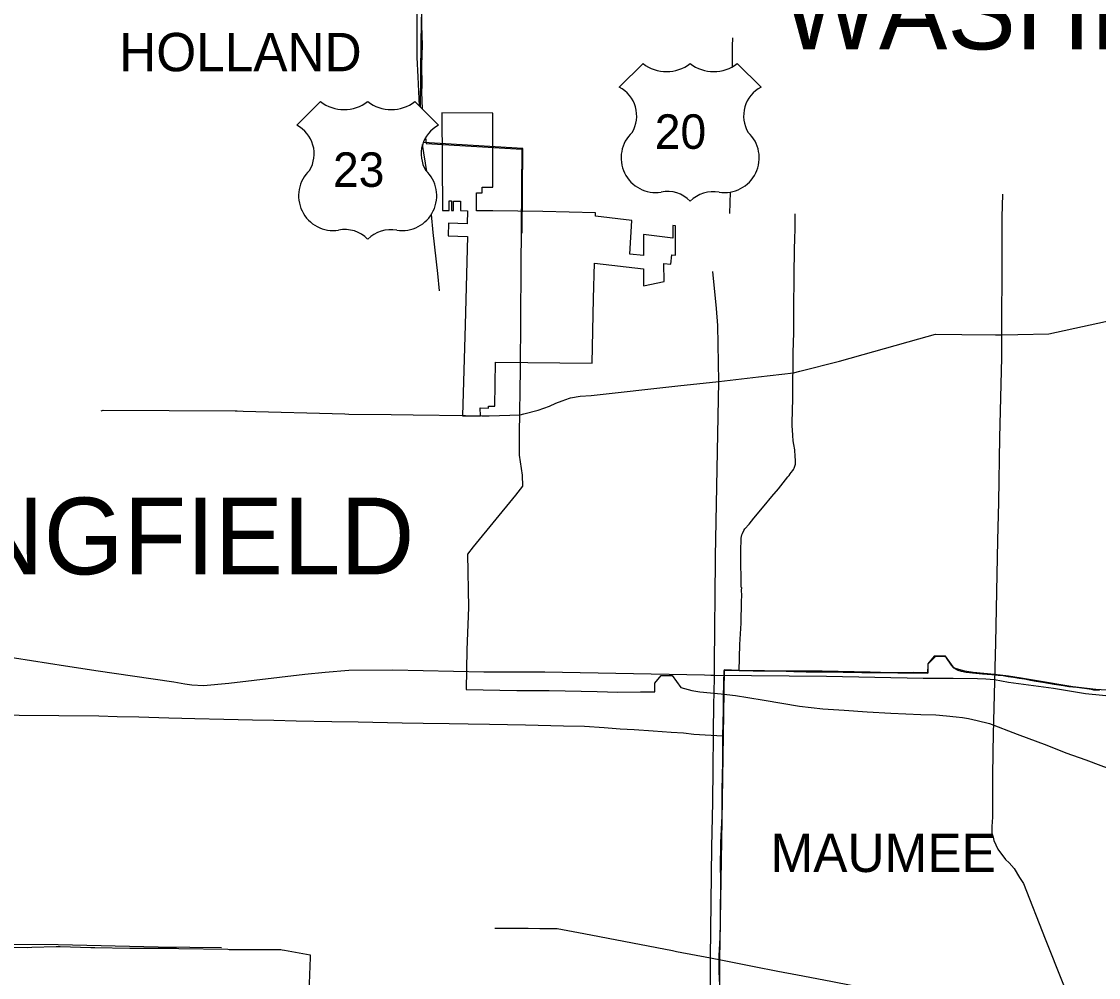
# Model space of a CAD drawing. Extents: x -232 to 448, y 619 to 1059.
# Drawn here: x 113.08 to 141.87, y 900.18 to 925.75 of the extents above; entities that cross this region are included whole.
import ezdxf

# ---------------------------------------------------------------- set-up
doc = ezdxf.new("R2010")
doc.units = 0
doc.layers.add('Default', color=7, linetype='Continuous')

msp = doc.modelspace()

# ---------------------------------------------------------------- linework, layer by layer
at = {"layer": 'Default'}
for p, q in [((129.69, 924.629), (129.056, 923.995)), ((129.69, 924.629), (129.056, 923.995)), ((132.845, 923.995), (132.211, 924.629)), ((132.845, 923.995), (132.211, 924.629)), ((121.069, 923.613), (120.435, 922.979)), ((121.069, 923.613), (120.435, 922.979)), ((124.224, 922.979), (123.59, 923.613)), ((124.224, 922.979), (123.59, 923.613)), ((124.312, 923.312), (124.329, 920.698)), ((125.678, 923.298), (124.312, 923.312)), ((125.391, 921.173), (125.392, 921.321)), ((125.392, 921.321), (125.675, 921.32)), ((125.242, 920.688), (125.242, 921.173)), ((125.242, 921.173), (125.391, 921.173)), ((124.329, 920.698), (124.508, 920.696)), ((124.508, 920.696), (124.51, 920.952)), ((124.51, 920.952), (124.574, 920.952)), ((124.574, 920.952), (124.571, 920.695)), ((124.571, 920.695), (124.622, 920.695)), ((124.622, 920.695), (124.625, 920.951)), ((124.625, 920.951), (124.815, 920.949)), ((124.815, 920.949), (124.812, 920.693)), ((124.49, 920.359), (124.479, 920.017)), ((124.99, 920.344), (124.49, 920.359)), ((130.489, 920.293), (130.489, 919.954)), ((130.558, 919.503), (130.557, 920.285)), ((124.479, 920.017), (124.997, 920.001)), ((129.703, 920.059), (129.702, 919.494)), ((130.489, 919.954), (129.703, 920.059)), ((129.702, 919.494), (129.342, 919.53)), ((128.391, 919.292), (129.701, 919.138)), ((130.253, 918.8), (130.246, 919.278)), ((130.246, 919.278), (130.435, 919.258)), ((130.435, 919.258), (130.461, 919.513)), ((130.461, 919.513), (130.558, 919.503)), ((129.701, 919.138), (129.7, 918.678)), ((129.7, 918.678), (130.253, 918.8)), ((125.731, 915.467), (125.745, 916.637)), ((125.561, 915.467), (125.731, 915.467))]:
    msp.add_line(p, q, dxfattribs=at)
for points in [[(123.714, 923.489), (123.675, 924.275), (123.65, 924.788), (123.649, 925.61), (123.641, 927.333), (123.627, 928.289), (123.622, 929.819), (123.618, 930.906), (123.63, 931.3), (123.629, 931.909), (123.655, 932.491), (123.72, 933.201), (123.778, 933.589), (123.941, 934.95), (124.022, 935.605), (124.069, 936.394), (124.077, 937.169), (124.04, 938.101), (124.013, 938.481)], [(123.745, 923.459), (123.764, 925.219), (123.875, 930.909), (124.356, 930.897), (124.373, 933.632)], [(123.806, 928.062), (123.767, 925.651), (123.782, 925.123), (123.772, 924.588), (123.778, 924.041), (123.766, 923.865)], [(132.078, 925.315), (132.074, 925.089), (132.07, 924.536)], [(123.766, 923.865), (123.79, 923.416)], [(125.675, 921.32), (125.678, 923.298)], [(123.913, 921.739), (123.795, 922.46)], [(126.457, 920.09), (126.481, 922.358), (123.82, 922.518)], [(123.876, 922.648), (123.896, 922.491)], [(123.896, 922.491), (126.452, 922.34)], [(126.452, 922.34), (126.428, 919.164), (126.409, 916.455)], [(132.02, 921.189), (132.002, 920.619)], [(139.303, 921.136), (139.284, 920.523), (139.286, 919.899)], [(124.812, 920.693), (125.001, 920.691)], [(125.001, 920.691), (124.99, 920.344)], [(125.672, 920.684), (125.242, 920.688)], [(128.42, 920.639), (127.016, 920.67), (125.672, 920.684)], [(124.253, 918.546), (124.205, 919.013), (124.083, 920.113), (124.033, 920.593)], [(128.42, 920.545), (128.42, 920.639)], [(129.388, 920.427), (128.42, 920.545)], [(129.342, 919.53), (129.388, 920.427)], [(132.263, 908.385), (132.282, 909.092), (132.31, 909.661), (132.325, 910.236), (132.332, 910.395), (132.326, 910.543), (132.333, 910.6), (132.313, 910.625), (132.313, 910.868), (132.309, 911.248), (132.306, 911.67), (132.31, 911.832), (132.314, 911.933), (132.321, 911.98), (132.33, 912.021), (132.349, 912.061), (132.387, 912.141), (132.416, 912.18), (132.529, 912.309), (132.65, 912.47), (132.925, 912.798), (133.13, 913.044), (133.309, 913.251), (133.436, 913.413), (133.565, 913.569), (133.597, 913.612), (133.628, 913.655), (133.653, 913.689), (133.691, 913.744), (133.716, 913.772), (133.735, 913.805), (133.752, 913.86), (133.763, 913.916), (133.768, 913.965), (133.767, 914.018), (133.754, 914.119), (133.745, 914.296), (133.723, 914.436), (133.706, 914.539), (133.696, 914.683), (133.682, 914.828), (133.675, 914.924), (133.678, 915.07), (133.687, 915.296), (133.694, 915.711), (133.696, 916.104), (133.701, 916.521), (133.707, 916.903), (133.718, 917.427), (133.721, 917.867), (133.721, 918.122), (133.725, 918.379), (133.735, 918.63), (133.732, 918.922), (133.734, 919.195), (133.74, 919.421), (133.742, 919.713), (133.749, 919.883), (133.759, 920.259), (133.759, 920.607)], [(130.557, 920.285), (130.489, 920.293)], [(124.997, 920.001), (124.939, 917.64)], [(139.286, 919.899), (139.286, 919.443), (139.275, 917.373)], [(139.707, 917.382), (140.54, 917.4), (142.541, 917.833), (146.021, 918.829), (149.248, 919.837)], [(128.369, 918.347), (128.391, 919.292)], [(131.717, 916.125), (131.694, 917.618), (131.657, 918.076), (131.555, 919.063)], [(128.329, 916.614), (128.369, 918.347)], [(124.939, 917.64), (124.863, 915.202)], [(133.88, 916.4), (134.947, 916.67), (137.061, 917.265)], [(137.061, 917.265), (137.511, 917.392), (138.212, 917.384)], [(138.212, 917.384), (139.116, 917.374)], [(139.116, 917.374), (139.275, 917.373)], [(139.275, 917.373), (139.269, 916.758), (139.224, 914.628), (139.189, 912.895)], [(139.275, 917.373), (139.707, 917.382)], [(126.409, 916.455), (126.376, 914.719), (126.381, 914.149), (126.463, 913.62), (126.468, 913.322), (126.284, 913.084), (125.153, 911.7), (124.995, 911.509)], [(125.745, 916.637), (128.329, 916.614)], [(132.774, 916.248), (133.715, 916.358), (133.88, 916.4)], [(130.619, 916.003), (131.717, 916.125)], [(131.625, 911.332), (131.626, 911.44), (131.717, 916.125)], [(131.717, 916.125), (132.774, 916.248)], [(127.721, 915.675), (127.751, 915.685), (128.008, 915.731), (128.308, 915.748), (130.619, 916.003)], [(126.502, 915.257), (126.889, 915.354), (127.19, 915.461), (127.36, 915.548), (127.526, 915.608), (127.721, 915.675)], [(115.201, 915.341), (115.258, 915.36), (118.784, 915.336), (118.838, 915.335)], [(118.838, 915.335), (119.001, 915.33)], [(119.001, 915.33), (121.716, 915.256)], [(121.716, 915.256), (121.825, 915.253), (122.956, 915.239)], [(122.956, 915.239), (123.548, 915.232)], [(123.548, 915.232), (124.948, 915.215)], [(124.863, 915.202), (125.342, 915.201), (125.341, 915.42), (125.561, 915.414)], [(124.948, 915.215), (125.379, 915.209)], [(125.379, 915.209), (125.578, 915.207), (126.408, 915.233), (126.502, 915.257)], [(125.561, 915.414), (125.561, 915.467)], [(115.144, 907.168), (111.936, 907.2), (111.904, 905.094), (110.356, 905.131), (104.888, 905.043), (104.921, 907.765), (104.984, 912.994), (105.011, 913.263)], [(139.189, 912.895), (139.169, 911.87), (139.11, 909.135), (139.094, 908.473)], [(124.995, 911.509), (125.024, 910.074), (124.981, 908.945)], [(131.6, 908.588), (131.625, 911.332)], [(124.981, 908.945), (124.962, 907.881)], [(112.422, 908.8), (113.34, 908.658), (114.256, 908.517), (115.129, 908.386), (116.045, 908.246), (117.144, 908.086), (117.44, 908.04), (117.632, 908.011), (117.941, 907.996), (118.622, 908.052), (120.651, 908.297), (121.189, 908.349), (121.829, 908.398), (122.999, 908.413), (125.437, 908.359), (127.066, 908.361), (131.334, 908.274)], [(131.59, 907.727), (131.597, 908.297), (131.6, 908.588)], [(141.894, 907.857), (141.745, 907.87), (141.676, 907.886), (141.551, 907.9), (141.286, 907.935), (141.077, 907.957), (140.933, 907.98), (140.684, 908.021), (140.378, 908.071), (140.196, 908.102), (140.045, 908.127), (139.89, 908.159), (139.75, 908.182), (139.597, 908.207), (139.454, 908.227), (139.315, 908.248), (139.18, 908.261), (139.017, 908.273), (138.768, 908.298), (138.502, 908.323), (138.331, 908.338), (138.202, 908.369), (138.115, 908.395), (138.06, 908.42), (138.025, 908.443), (137.987, 908.471), (137.937, 908.533), (137.803, 908.735), (137.759, 908.77), (137.507, 908.768), (137.307, 908.558), (137.299, 908.311), (136.502, 908.322), (136.066, 908.327), (135.539, 908.335), (135.04, 908.339), (134.526, 908.347), (134.05, 908.347), (133.723, 908.358), (133.304, 908.371), (132.631, 908.371), (132.263, 908.385)], [(139.082, 908.285), (138.512, 908.338), (138.294, 908.374), (138.005, 908.454), (137.772, 908.779), (137.477, 908.777), (137.304, 908.575), (137.307, 908.334), (136.926, 908.338), (136.321, 908.334)], [(132.263, 908.397), (131.858, 908.408), (131.834, 906.654), (131.798, 904.383)], [(132.263, 908.385), (131.848, 908.392), (131.836, 907.685), (131.831, 907.33), (131.819, 906.639)], [(136.321, 908.334), (135.762, 908.35), (134.482, 908.378), (133.615, 908.378), (132.263, 908.397)], [(139.092, 908.365), (139.087, 908.15), (139.086, 908.096)], [(139.094, 908.473), (139.092, 908.365)], [(129.019, 907.817), (129.625, 907.821), (130.005, 907.818), (130.002, 908.058), (130.176, 908.26), (130.471, 908.262), (130.703, 907.937), (130.992, 907.857), (131.21, 907.822), (131.78, 907.769)], [(131.334, 908.274), (131.5, 908.27)], [(131.5, 908.27), (131.594, 908.268), (134.598, 908.244), (137.176, 908.188), (137.98, 908.185)], [(137.98, 908.185), (138.635, 908.183), (138.856, 908.173), (139.087, 908.15)], [(139.086, 908.096), (139.052, 906.689)], [(144.422, 907.737), (143.619, 907.766), (142.981, 907.8), (142.366, 907.845), (141.796, 907.882), (141.178, 907.958), (140.23, 908.114), (139.796, 908.19), (139.463, 908.238), (139.082, 908.285)], [(139.087, 908.15), (139.457, 908.085), (140.661, 907.922), (141.519, 907.779), (142.519, 907.677), (143.54, 907.636), (144.499, 907.595), (145.173, 907.534), (145.663, 907.473), (146.091, 907.432), (146.561, 907.248), (147.234, 907.003), (147.847, 906.799), (148.239, 906.665), (149.255, 906.227), (149.806, 906.044), (150.398, 905.819), (151.174, 905.554), (151.746, 905.39), (152.157, 905.252), (152.247, 905.223)], [(124.962, 907.881), (126.313, 907.861), (127.181, 907.862), (128.461, 907.833), (129.019, 907.817)], [(131.587, 907.565), (131.59, 907.727)], [(131.78, 907.769), (132.162, 907.722), (132.494, 907.674), (132.928, 907.597), (133.876, 907.442), (134.495, 907.365), (135.065, 907.329), (135.68, 907.283), (136.317, 907.249), (137.121, 907.22)], [(131.496, 900.597), (131.496, 900.704), (131.533, 903.665), (131.553, 904.875), (131.587, 907.565)], [(131.819, 906.639), (131.045, 906.684), (130.776, 906.715), (130.443, 906.739), (129.962, 906.769), (129.454, 906.802), (129.082, 906.827), (128.653, 906.862), (128.122, 906.893), (127.561, 906.904), (126.547, 906.927), (125.582, 906.948), (125.016, 906.959), (124.511, 906.965), (123.817, 906.974), (123.253, 906.988), (122.075, 907.012), (121.372, 907.024), (120.421, 907.041), (119.822, 907.053), (119.252, 907.062), (118.485, 907.08), (117.706, 907.099), (117.011, 907.118), (116.209, 907.141), (115.631, 907.156), (115.144, 907.168)], [(137.121, 907.22), (137.515, 907.208), (137.799, 907.177), (138.058, 907.154), (138.23, 907.132), (138.391, 907.108), (138.623, 907.054), (138.951, 906.973), (139.689, 906.688), (140.487, 906.392), (140.997, 906.194)], [(131.819, 906.639), (131.816, 905.94), (131.798, 905.198), (131.793, 904.502), (131.765, 903.789), (131.754, 903.088), (131.763, 902.886), (131.764, 902.438), (131.757, 902.136), (131.754, 901.846), (131.752, 901.544), (131.745, 901.242), (131.719, 900.768), (131.718, 900.344), (131.735, 899.98), (131.751, 899.735), (131.762, 899.521), (131.771, 899.347), (131.792, 899.12), (131.809, 899.005), (131.835, 898.86), (131.859, 898.693)], [(139.051, 906.635), (139.042, 906.272), (139.032, 905.499), (139.031, 905.06)], [(139.052, 906.689), (139.051, 906.635)], [(140.997, 906.194), (141.529, 906.002), (141.933, 905.848), (142.438, 905.661), (142.741, 905.547), (142.907, 905.489)], [(139.031, 905.06), (139.029, 904.468), (139.019, 904.222), (139.019, 904.195)], [(131.798, 904.383), (131.736, 900.651)], [(139.019, 904.195), (139.017, 904.038), (139.049, 903.935), (139.07, 903.844), (139.177, 903.615), (139.378, 903.341), (139.476, 903.248)], [(139.476, 903.248), (139.616, 903.093), (139.758, 902.857), (139.861, 902.693), (140.444, 901.213), (141.366, 898.885), (141.391, 898.784), (141.572, 898.301)], [(125.727, 901.504), (126.623, 901.498), (126.929, 901.496)], [(126.929, 901.496), (127.393, 901.494), (128.111, 901.357), (130.48, 900.901), (130.587, 900.881)], [(108.162, 901.123), (111.244, 901.071), (114.058, 901.063), (116.733, 901), (118.426, 900.988)], [(108.187, 901.063), (108.536, 901.055), (108.571, 901.054), (108.645, 901.053), (110.106, 901.035), (110.155, 901.034), (110.214, 901.033), (111.242, 901.012), (111.283, 901.011), (111.351, 901.01), (112.433, 900.995), (112.472, 900.994), (112.541, 900.994), (113.244, 900.986), (113.247, 900.986), (113.355, 900.989), (114.005, 901.01), (114.057, 901.012)], [(114.057, 901.012), (114.111, 901.01), (114.93, 900.987), (114.978, 900.986), (115.04, 900.985), (115.969, 900.97), (116.001, 900.969), (116.078, 900.969), (117.171, 900.962), (117.223, 900.962), (117.279, 900.961), (118.59, 900.935), (118.626, 900.934), (118.7, 900.934), (120.011, 900.926), (120.045, 900.925), (120.11, 900.913), (120.796, 900.784)], [(130.587, 900.881), (131.496, 900.704)], [(120.796, 900.784), (120.793, 900.72), (120.769, 900.023), (120.77, 899.926), (120.779, 898.736), (120.774, 898.651), (120.716, 897.732), (120.711, 897.665), (120.406, 893.385)], [(131.496, 900.704), (131.813, 900.642)], [(132.351, 895.814), (132.339, 895.855), (132.051, 896.952), (131.88, 897.612), (131.736, 898.227), (131.63, 898.795), (131.496, 900.003), (131.496, 900.597)], [(131.736, 900.651), (131.736, 900.057), (131.749, 899.611), (131.782, 899.306), (131.824, 898.978), (131.87, 898.648), (131.947, 898.111), (132.006, 897.67), (132.045, 897.505), (132.206, 896.954), (132.369, 896.334), (132.523, 895.837)], [(131.813, 900.642), (132.66, 900.478)], [(132.66, 900.478), (133.294, 900.354)], [(133.294, 900.354), (133.823, 900.251)], [(133.823, 900.251), (134.707, 900.08), (138.603, 899.32), (141.127, 898.835)]]:
    msp.add_lwpolyline(points, dxfattribs=at)
for centre, radius, start, end in [((130.32, 925.431), 1.019, 231.813, 308.187), ((130.32, 925.431), 1.019, 231.813, 308.187), ((131.581, 925.431), 1.019, 231.813, 308.187), ((131.581, 925.431), 1.019, 231.813, 308.187), ((128.659, 923.23), 0.862, 329.1175, 62.6108), ((128.659, 923.23), 0.862, 329.1175, 62.6108), ((133.242, 923.23), 0.862, 117.3892, 210.8825), ((133.242, 923.23), 0.862, 117.3892, 210.8825), ((121.699, 924.414), 1.019, 231.813, 308.187), ((121.699, 924.414), 1.019, 231.813, 308.187), ((122.96, 924.414), 1.019, 231.813, 308.187), ((122.96, 924.414), 1.019, 231.813, 308.187), ((120.038, 922.213), 0.862, 329.1175, 62.6108), ((120.038, 922.213), 0.862, 329.1175, 62.6108), ((124.621, 922.213), 0.862, 117.3892, 210.8825), ((124.621, 922.213), 0.862, 117.3892, 210.8825), ((130.034, 922.107), 0.93, 133.0046, 278.7282), ((130.034, 922.107), 0.93, 133.0046, 278.7282), ((131.867, 922.107), 0.93, 261.2718, 46.9954), ((131.867, 922.107), 0.93, 261.2718, 46.9954), ((121.413, 921.09), 0.93, 133.0046, 278.7282), ((121.413, 921.09), 0.93, 133.0046, 278.7282), ((123.246, 921.09), 0.93, 261.2718, 46.9954), ((123.246, 921.09), 0.93, 261.2718, 46.9954), ((130.346, 920.373), 0.832, 43.4177, 101.8742), ((130.346, 920.373), 0.832, 43.4177, 101.8742), ((131.572, 920.318), 0.883, 79.9613, 134.7468), ((131.572, 920.318), 0.883, 79.9613, 134.7468), ((121.725, 919.356), 0.832, 43.4177, 101.8742), ((121.725, 919.356), 0.832, 43.4177, 101.8742), ((122.951, 919.301), 0.883, 79.9613, 134.7468), ((122.951, 919.301), 0.883, 79.9613, 134.7468)]:
    msp.add_arc(centre, radius, start, end, dxfattribs=at)

# ---------------------------------------------------------------- texts
for s, height, p in [('WASHINGTON', 2.052, (133.407, 925.008)), ('HOLLAND', 1.026, (115.688, 924.421)), ('20', 0.9234, (130.005, 922.346)), ('23', 0.9234, (121.403, 921.329)), ('SPRINGFIELD', 2.052, (105.282, 910.965)), ('MAUMEE', 1.026, (133.098, 903.003))]:
    msp.add_text(s, height=height, dxfattribs=at).set_placement(p)

doc.saveas('drawing.dxf')
